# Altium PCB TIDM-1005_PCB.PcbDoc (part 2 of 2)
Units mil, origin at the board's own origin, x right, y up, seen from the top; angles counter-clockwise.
Board outline 3505 x 2975 mil, 2 copper layers (Top Layer, Bottom Layer), stack 62 mil thick; 159 components, 97 nets, 498 pads, 124 vias.
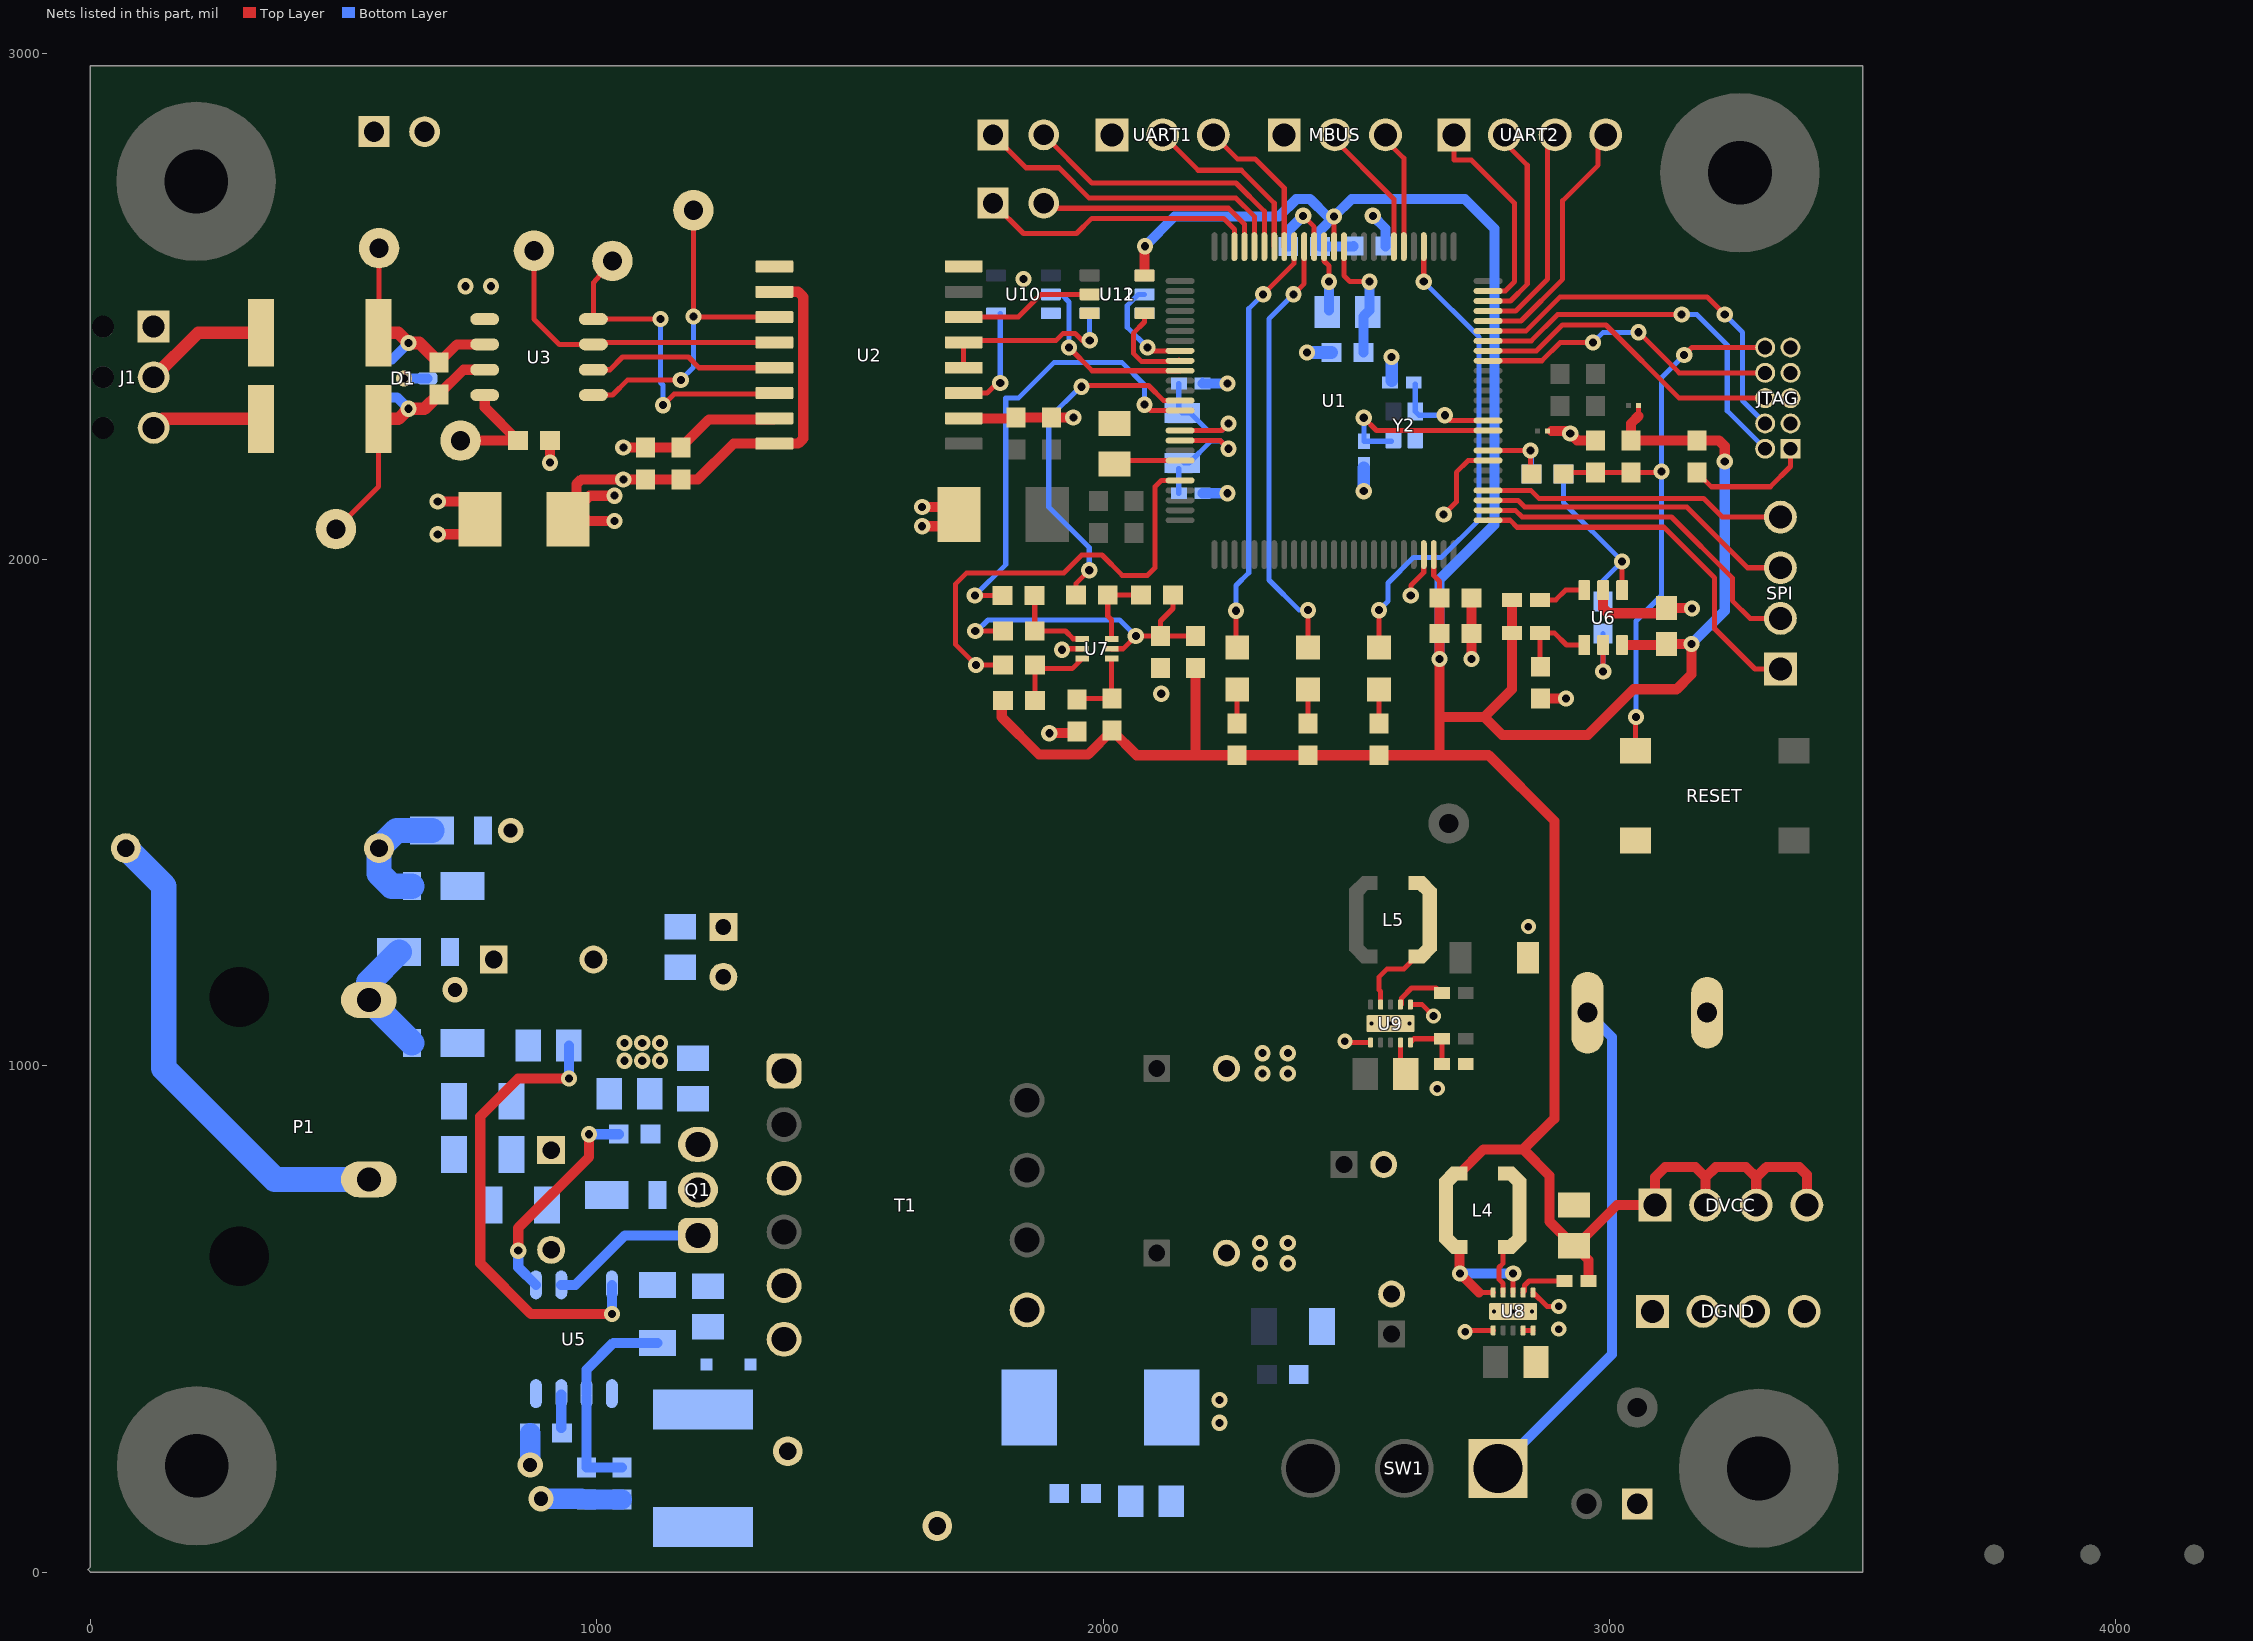
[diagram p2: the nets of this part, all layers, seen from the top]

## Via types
v1: diameter 32, hole 16, Top Layer to Bottom Layer, tented both sides, 88 vias
v2: diameter 32, hole 16, Top Layer to Bottom Layer, 19 vias
v3: diameter 30, hole 15, Top Layer to Bottom Layer, 7 vias
v4: diameter 19.68, hole 7.87, Top Layer to Bottom Layer, 6 vias
v5: diameter 50, hole 28, Top Layer to Bottom Layer, tented both sides, 3 vias
v6: diameter 50, hole 28, Top Layer to Bottom Layer, 1 vias

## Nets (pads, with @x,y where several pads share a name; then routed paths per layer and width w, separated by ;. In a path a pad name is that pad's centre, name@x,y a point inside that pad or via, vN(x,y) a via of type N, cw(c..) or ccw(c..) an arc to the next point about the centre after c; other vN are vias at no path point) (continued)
DGND: C1.1 C2.1 C3.2 C4.1 C5.1 C6.2 C7.1 C8.2 C9.1 C10.2 C15.2 C16.1 C26.2 C27.2 C28.2 C30.1 C31.1 C33.1 C34.2 C35.2 C36.2 C37.1 C38.1 C39.2 C40.2 D9.2 D10.2 DGND.1 DGND.2 DGND.3 DGND.4 J2.1 J3.2 JTAG.3 JTAG.5 JTAG.7 JTAG.9 MBUS.1 NT2.1 R2.2 R16.2 R17.2 R35.2 R93.2 RESET.3 U1.15 U1.72 U1.82 U2.2 U2.8 U6.2 U7.2 U8.1 U8.4 U8.5 U8.6 U8.11@2810,515 U9.1 U9.4 U9.6 U9.11@2567.72,1083.54 U10.3 U11.3 U12.3 UART1.1 Y2.2 | length 1959.5
  Top Layer w10: D10.2@1715.79,2088.81 D10.2@1715.79,2095.81 ; v1@1920.8,1823.81 U7.2@1958.66,1823.81 ; v1(2395.3,2678.81) 2416.93,2657.17 U1.15@2416.93,2617.94 ; v3@2480.12,1046.14 U9.1@2528.35,1046.14 ; C37.1@2587.4,993.86 U9.4@2587.4,1046.14 ; U9.6@2607.09,1120.94 2630.32,1120.94 v3(2652.72,1098.54) ; v1(2607.8,1928.81) 2607.8,1948.81 2633.47,1974.48 U1.72@2633.47,2009.67 ; v1(2672.8,2088.81) 2697.8,2113.81 2697.8,2172.27 2721.22,2195.7 U1.82@2760.43,2195.7 ; v3@2717.6,477.6 U8.1@2770.63,477.6 ; U8.4@2829.69,477.6 U8.5@2849.37,477.6 ; U8.6@2849.37,552.4 2876.77,525 v3(2900,525)
  Top Layer w20: v1(1642.8,2065.81) 1692.8,2065.81 D10.2@1715.79,2088.81 ; v1(1642.8,2103.81) 1707.8,2103.81 D10.2@1715.79,2095.81 ; U2.2@1724.8,2278.81 1826.3,2278.81 C15.2@1827.8,2280.3 C16.1@1897.8,2280.3 v1(1941.3,2280.3) ; v1@1900.39,1657.47 R93.2@1948.9,1657.47 ; v1(2727.8,1803.81) C8.2@2727.8,1853.81 C7.1@2727.8,1923.81 ; C34.2@2864.29,1725.3 v1(2914.29,1725.3) ; 2885.8,2253.81 2917.8,2253.81 v1(2922.8,2248.81) 2936.3,2235.3 C3.2@2972.8,2235.3 ; U6.2@2987.8,1939.44 2987.8,1903.81 2997.8,1893.81 3102.36,1893.81 C33.1@3112.8,1904.24 v1@3162.36,1904.24
  Bottom Layer w10: C1.1@2196.83,2347.47 C1.1@2196.83,2354.33
  Bottom Layer w20: C2.1@2196.83,2130.93 v1(2245.67,2130.93) ; C1.1@2196.83,2347.47 v1(2245.67,2347.47) ; C9.1@2365.75,2617.94 2365.75,2649.26 v1(2395.3,2678.81) ; v1(2532.8,2678.81) 2557.8,2653.81 C10.2@2557.8,2618.81
  Bottom Layer w25: v1(2402.8,2408.81) C6.2@2451.3,2408.81 ; v1(2515,2135) C4.1@2515,2181.38 ; C5.1@2570,2353.62 v1(2570,2400)
  other v1: 2310,610 2365,610 2310,650 2365,650 2315,985 2365,985 2315,1025 2365,1025 1893.9,1656.9 2115,1735 1918.9,1821.9 3163.27,1903.33
  other v2: 2230,295 2230,340 1842.8,2553.81
  other v3: 2715,475 2900,480 2660,955 2477.72,1048.54 2840,1275
  other v4: 2772.6,515 2810,515 2847.4,515 2530.32,1083.54 2567.72,1083.54 2605.12,1083.54
DVCC: C7.2 C8.1 C9.2 C10.1 C33.2 C35.1 DVCC.1 DVCC.2 DVCC.3 DVCC.4 L4.2 NT1.1 R1.2 R3.2 R5.2 R6.2 R25.2 R29.2 R30.2 R33.2 R90.2 R91.2 R98.2 U1.13 U1.73 U6.6 U8.8 U8.10 U12.5 | length 7621.8
  Top Layer w10: U1.13@2456.3,2617.94 v1(2456.3,2677.31) ; U1.73@2653.15,2009.67 2653.15,1968.45 2664.8,1956.8 C7.2@2664.8,1923.81 ; 2742.6,552.4 U8.10@2770.63,552.4 ; U8.8@2810,552.4 v2(2810,590) ; 3057.8,2283.81 NT1.1@3057.8,2303.81
  Top Layer w20: R91.2@1800,1722.15 1800,1688.65 1873.65,1615 1970.49,1615 R98.2@2017.8,1662.31 2066.6,1613.5 R25.2@2264.93,1613.5 R6.2@2405,1613.5 R5.2@2544.93,1613.5 2761.5,1613.5 2891.46,1483.54 2891.46,895 ; U12.5@2081.93,2561.21 v2@2081.93,2617.94 ; 2182.8,1616.3 R90.2@2182.8,1785.81 ; 2664.8,1613.7 2664.8,1688.81 ; C7.2@2664.8,1923.81 C8.1@2664.8,1853.81 v1(2664.8,1803.81) 2664.8,1688.81 ; v2@2704,591 L4.2@2704,642.5 ; L4.2@2704,787.5 2751.5,835 2830,835 ; v2(2705,590) 2742.6,552.4 ; R29.2@2807.68,1920.3 R30.2@2807.68,1855.3 2807.68,1743.69 2752.8,1688.81 ; 2890,895 2830,835 ; C35.1@2929.46,645 2881.5,692.96 2881.5,783.5 2830,835 ; R33.2@2958.62,575 2958.62,616.38 C35.1@2930,645 2935,645 3015,725 DVCC.1@3090,725 3090,780 3110,800 3170,800 3190,780 ; U6.6@3025.2,1831.17 3110.59,1831.17 C33.2@3112.8,1833.37 v1(3162.36,1833.37) 3162.36,1773.37 3132.8,1743.81 3047.8,1743.81 2957.8,1653.81 2787.8,1653.81 2752.8,1688.81 ; 3057.8,2283.81 3042.8,2268.81 R1.2@3042.8,2235.3 R3.2@3172.8,2235.3 3216.3,2235.3 3227.8,2223.81 v1(3227.8,2193.81) ; DVCC.2@3190,725 3190,780 ; DVCC.3@3290,725 3290,780 ; DVCC.4@3372.09,727.91 DVCC.4@3375,725 ; DVCC.4@3390,725 3390,785 3375,800 3310,800 3290,780 ; 2664.8,1688.81 2752.8,1688.81 ; 3190,780 3210,800 3270,800 3290,780
  Bottom Layer w20: v2(2082.8,2618.81) 2141.3,2677.31 2347.13,2677.31 2381.63,2711.81 2408.97,2711.81 2443.46,2677.31 v1(2456.3,2677.31) ; C10.1@2494.8,2618.81 2493.94,2617.94 C9.2@2428.74,2617.94 2428.74,2649.75 v1(2456.3,2677.31) ; v1(2664.8,1803.81) 2664.8,1960.81 2772.8,2068.81 2772.8,2653.81 2714.8,2711.81 2490.8,2711.81 v1(2456.3,2677.31) ; v2(2705,590) v2(2810,590) ; v1(3162.36,1833.37) 3227.8,1898.81 v1(3227.8,2193.81)
HFXIN: C5.2 U1.86 Y2.1 | length 205.7
  Top Layer w10: v1(2675,2285) 2685.56,2274.44 U1.86@2760.43,2274.44
  Bottom Layer w10: C5.2@2616.65,2346.97 Y2.1@2616.65,2292.56 2624.21,2285 v1(2675,2285)
HFXOUT: C4.2 U1.85 Y2.3 | length 356.8
  Top Layer w10: v1(2515,2280) 2540.25,2254.75 U1.85@2760.43,2254.75
  Bottom Layer w10: v1(2515,2280) C4.2@2515,2233.62 Y2.3@2569.53,2233.62
I2C_SCL: R96.2 U1.39 | length 905.2
  Top Layer w10: v1(1746.8,1928.81) R96.2@1801.3,1928.81 ; v1(2081.8,2305.81) 2093.48,2294.12 U1.39@2152.17,2294.12
  Bottom Layer w10: v1(1746.8,1928.81) 1807.8,1989.81 1807.8,2318.81 1832.8,2318.81 1902.8,2388.81 2037.8,2388.81 2081.8,2344.81 v1(2081.8,2305.81)
I2C_SDA: R97.2 U1.38 | length 691.8
  Top Layer w10: R97.2@1946.3,1929.81 1946.3,1952.31 v1(1972.8,1978.81) ; v1(1957.3,2341.31) 1959.8,2343.81 2089.8,2343.81 2119.8,2313.81 U1.38@2152.17,2313.81
  Bottom Layer w10: v1(1957.3,2341.31) 1955.3,2341.31 1892.8,2278.81 1892.8,2103.81 1972.8,2023.81 v1(1972.8,1978.81)
INTERRUPT: R92.2 U1.46 | length 883.7
  Top Layer w10: v1@1743.9,1796.9 1708.9,1831.9 1708.9,1951.9 1730.8,1973.81 1922.8,1973.81 1957.8,2008.81 1997.8,2008.81 2037.8,1968.81 2087.8,1968.81 2102.8,1983.81 2102.8,2143.81 2115.32,2156.33 U1.46@2152.17,2156.33 ; v1(1748.9,1791.9) R92.2@1808.27,1791.9
LED1: LED1.2 U1.4 | length 951
  Top Layer w10: LED1.2@2545,1826.34 v1(2545,1900) ; v1(2633.47,2548.81) U1.4@2633.47,2617.94
  Bottom Layer w10: v1(2545,1900) 2562.8,1917.8 2562.8,1953.81 2612.8,2003.81 2667.8,2003.81 2742.8,2078.81 2742.8,2439.48 v1(2633.47,2548.81)
LED2: LED2.2 U1.16 | length 862.7
  Top Layer w10: v1(2376.3,2523.81) 2397.25,2544.75 U1.16@2397.25,2617.94 ; LED2.2@2405,1826.34 v1(2405,1900)
  Bottom Layer w10: v1(2376.3,2523.81) 2327.8,2475.3 2327.8,1959.51 2387.3,1900 v1(2405,1900)
LED3: LED3.2 U1.17 | length 838.9
  Top Layer w10: LED3.2@2262.8,1828.54 v1(2262.8,1898.81) ; v1(2316.3,2523.81) 2377.56,2585.07 U1.17@2377.56,2617.94
  Bottom Layer w10: v1(2262.8,1898.81) 2262.8,1948.81 2287.8,1973.81 2287.8,2495.3 v1(2316.3,2523.81) v1@2317.67,2522.44
MBUS_RXD: MBUS.3 U1.6 | length 240
  Top Layer w10: MBUS.3@2547.8,2838.81 2594.1,2792.51 U1.6@2594.1,2617.94
MBUS_TXD: MBUS.2 U1.7 | length 273.3
  Top Layer w10: MBUS.2@2447.8,2838.81 2574.41,2712.19 U1.7@2574.41,2617.94
NetC17_1: C17.1 C18.2 C32.1 D11.1 TP3.1 U2.10 U2.16 U3.8 | length 1258.8
  Top Layer w20: TP3.1@746.09,2234.83 C32.1@844.6,2234.83 778.81,2300.62 U3.8@778.81,2324.83 ; v1(1034.83,2076.09) 983.57,2076.09 D11.1@959.83,2099.83 ; v1(1034.83,2126.09) 986.09,2126.09 D11.1@959.83,2099.83 ; 1267.99,2226.73 1199.6,2158.33 C18.2@1166.09,2158.33 C17.1@1096.09,2158.33 v1(1052.59,2158.33) 969.6,2158.33 959.83,2148.57 D11.1@959.83,2099.83 ; 1270.07,2228.81 U2.16@1350.79,2228.81 1397.8,2228.81 1407.8,2238.81 1407.8,2518.81 1397.8,2528.81 U2.10@1350.79,2528.81
NetC22_1: C22.1 R13.2 R15.1
NetC22_2: C22.2 C24.1 L3.2 R12.2 R13.1 R14.1 T1.1
NetC23_1: C23.1 D3.1 D4.1 L3.1 R12.1
NetC25_1: C25.1 R16.1
NetC25_2: C25.2 D9.1 T1.7
NetC29_2: C29.2 D8.1 U5.1
NetC31_2: C31.2 R90.1 R94.2 R95.2 U7.5 | length 661.3
  Top Layer w10: v1(1747.66,1858.81) R95.2@1802.17,1858.81 ; U7.5@2016.93,1823.81 2039.8,1823.81 v1(2064.8,1848.81) C31.2@2113.66,1848.81 ; R94.2@2138.29,1929.81 2138.29,1903.3 2113.66,1878.67 C31.2@2113.66,1848.81 ; R90.1@2182.8,1848.81 C31.2@2113.66,1848.81
  Bottom Layer w10: v1(1747.66,1858.81) 1750.8,1858.81 1772.66,1880.67 2032.93,1880.67 v1(2064.8,1848.81)
NetC34_1: C34.1 R30.1 U6.4 | length 168.2
  Top Layer w10: C34.1@2864.29,1788.29 2862.8,1786.8 R30.1@2862.8,1855.3 2891.3,1855.3 2915.43,1831.17 U6.4@2950.4,1831.17
NetD1_1: D1.1 R7.1 R8.1 TP8.1 U3.7 | length 569
  Top Layer w10: TP8.1@485,2060 569.3,2144.3 R8.1@569.3,2277.72
  Top Layer w20: R7.1@688.16,2326.22 736.77,2374.83 U3.7@778.81,2374.83
  Top Layer w25: R8.1@569.3,2277.72 608.16,2277.72 v1(628.16,2297.72) 659.66,2297.72 R7.1@688.16,2326.22
  Bottom Layer w20: D1.1@570.92,2320.32 605.56,2320.32 v1(628.16,2297.72)
NetD1_2: D1.2 R7.2 R9.1 TP9.1 U3.6 | length 486.8
  Top Layer w10: R9.1@569.3,2447.72 570,2448.42 TP9.1@570,2615
  Top Layer w20: R7.2@688.16,2389.22 723.78,2424.83 U3.6@778.81,2424.83
  Top Layer w25: R9.1@569.3,2447.72 608.16,2447.72 v1(628.16,2427.72) 649.66,2427.72 R7.2@688.16,2389.22
  Bottom Layer w20: D1.2@570.92,2395.12 595.56,2395.12 v1(628.16,2427.72)
NetD3_2: D3.2 D5.1 F1.1 | length 244.5
  Bottom Layer w50: D3.2@634.8,1355 595,1355 570,1380 F1.1@570,1430 605,1465 D5.1@674.8,1465
NetD4_2: D4.2 D6.1 P1.1 | length 239.8
  Bottom Layer w50: P1.1@549.92,1129.88 D4.2@634.8,1045 ; P1.1@549.92,1130 549.92,1165.12 D6.1@609.8,1225
NetD7_1: D7.1 R15.2
NetD7_2: D7.2 Q1.2 T1.3
NetD8_2: D8.2 R18.1
NetF1_2: F1.2 P1.2 | length 961.8
  Bottom Layer w50: F1.2@70,1430 145,1355 145,995 364.33,775.67 P1.2@549.92,775.67
NetJ1_2: J1.2 R9.2 | length 248.4
  Top Layer w25: J1.2@125,2360 212.72,2447.72 R9.2@337.02,2447.72
NetJ1_3: J1.3 R8.2 | length 219.4
  Top Layer w25: J1.3@125,2260 142.72,2277.72 R8.2@337.02,2277.72
NetJ3_1: J3.1 SW1.1 | length 1027.3
  Bottom Layer w10: J3.1@2946.89,1145 J3.1@2956.89,1155
  Bottom Layer w20: SW1.1@2780.04,205 2946.89,371.85 3005,429.96 3005,1056.89 J3.1@2956.89,1105
NetJTAG_1: JTAG.1 R3.1 | length 248.4
  Top Layer w10: R3.1@3172.8,2172.31 3201.3,2143.81 3317.8,2143.81 3357.8,2183.81 JTAG.1@3357.8,2218.81
NetL1_1: L1.1 U1.14 | length 134.6
  Top Layer w10: U1.14@2436.62,2617.94 2436.62,2589.67 2446.3,2579.98 v1(2446.3,2548.81)
  Bottom Layer w10: L1.1@2442.8,2488.81 L1.1@2446.3,2492.31
  Bottom Layer w20: L1.1@2446.3,2492.31 v1(2446.3,2548.81)
NetL4_1: L4.1 U8.9 | length 99.3
  Top Layer w10: U8.9@2790.32,552.4 2790.32,570.09 2782,578.4 2782,601.6 2790.32,609.91 2790.32,636.82 L4.1@2796,642.5
NetL5_1: L5.1 U9.9 | length 146.5
  Top Layer w10: U9.9@2548.03,1120.94 2548.03,1146.99 2544.72,1150.31 2544.72,1175.14 2561.12,1191.54 2594.22,1191.54 L5.1@2618.72,1216.04
NetLED1_1: LED1.1 R5.1 | length 67.1
  Top Layer w10: R5.1@2545,1676.56 LED1.1@2545,1743.66
NetLED2_1: LED2.1 R6.1 | length 67.2
  Top Layer w10: R6.1@2405,1676.5 LED2.1@2405,1743.66
NetLED3_1: LED3.1 R25.1 | length 67.1
  Top Layer w10: R25.1@2265,1676.56 LED3.1@2265,1743.66
NetQ1_1: Q1.1 U5.6 | length 310.6
  Bottom Layer w20: U5.6@930,567.28 957.72,567.28 1055.67,665.24 Q1.1@1200,665.24
NetQ1_3: Q1.3 R20.2 R23.1 R24.1
NetR2_1: R2.1 U1.44 | length 132.2
  Top Layer w10: R2.1@2022.8,2188.81 2029.69,2195.7 U1.44@2152.17,2195.7
NetR4_2: R4.2 R31.2 U1.83 | length 183.5
  Top Layer w10: U1.83@2760.43,2215.38 v1(2844.37,2215.38) 2844.37,2170.74 R4.2@2846.3,2168.81
  Bottom Layer w10: R31.2@2846.3,2168.81 2846.3,2213.45 v1(2844.37,2215.38) v1@2847.8,2218.81
NetR14_2: R14.2 U5.8 | length 919.8
  Top Layer w20: v2(945,975) 845,975 770,900 770,610 870,510 v2(1030,510)
  Bottom Layer w20: v2(945,975) R14.2@945,1040 ; v2(1030,510) U5.8@1030,567.28
NetR18_2: R18.2 R19.1 T1.5
NetR19_2: R19.2 R21.1 R22.1 U5.2 | length 418.2
  Bottom Layer w20: U5.2@980,345.52 R21.1@980,206.5 R22.1@1050,206.5 ; U5.2@980,352.72 980,400 1032.91,452.91 R19.2@1120,452.91
NetR20_1: R20.1 U5.5 | length 428.7
  Top Layer w20: v2(845,635) 845,680 985,820 v2(985,865)
  Bottom Layer w20: v2(845,635) 845,602.28 U5.5@880,567.28 ; v2(985,865) R20.1@1043.5,865
NetR29_1: R29.1 U6.3 | length 95.5
  Top Layer w10: R29.1@2862.8,1920.3 2894.29,1920.3 2913.43,1939.44 U6.3@2950.4,1939.44
NetR32_2: R32.2 U6.5 | length 127.4
  Top Layer w10: v1(2987.8,1778.81) U6.5@2987.8,1831.17
  Bottom Layer w10: v1(2987.8,1778.81) R32.2@2987.8,1853.81
NetR33_1: R33.1 U8.7 | length 97.4
  Top Layer w10: U8.7@2829.69,552.4 2832.45,555.17 2832.45,566.06 2841.39,575 R33.1@2911.38,575
NetR34_2: R34.2 R35.1 U9.5 | length 115.1
  Top Layer w10: U9.5@2607.09,1046.14 2614.49,1053.54 R34.2@2669.09,1053.54 R35.1@2669.09,1003.54
NetR36_1: R36.1 U9.7 | length 105.3
  Top Layer w10: U9.7@2589.72,1120.94 2589.72,1134.16 2609.1,1153.54 2657.72,1153.54 R36.1@2669.09,1142.17
NetR91_1: R91.1 R92.1 U7.3 | length 159.6
  Top Layer w10: R91.1@1865.39,1721.9 1865.39,1776.97 1872.86,1784.44 1938.98,1784.44 U7.3@1958.66,1804.12
NetR93_1: R93.1 R98.1 U7.4 | length 154.2
  Top Layer w10: R93.1@1942.8,1725.3 R98.1@2017.8,1725.3 2016.93,1726.17 U7.4@2016.93,1804.12
NetR94_1: R94.1 R97.1 U7.6 | length 155.5
  Top Layer w10: U7.6@2016.93,1843.49 2016.93,1880.67 2009.29,1888.31 R97.1@2009.29,1929.81 R94.1@2075.3,1929.81
NetR95_1: R95.1 R96.1 U7.1 | length 169
  Top Layer w10: R96.1@1865.16,1927.94 R95.1@1865.16,1858.81 1925.8,1858.81 1941.11,1843.49 U7.1@1958.66,1843.49
NetRT1_1: RT1.1 U5.3 | length 66.2
  Bottom Layer w20: RT1.1@930,285 U5.3@930,351.22
NetTP4_1: TP4.1 U2.14 U3.4 | length 664.8
  Top Layer w10: TP4.1@1031.09,2589.83 993.37,2547.11 U3.4@993.37,2474.83 v1(1126.09,2474.83) ; v1(1131.09,2304.83) 1153.09,2326.83 1350.79,2326.83 U2.14@1350.79,2328.81
  Bottom Layer w10: v1(1126.09,2474.83) 1126.09,2349.83 1131.09,2344.83 v1(1131.09,2304.83)
NetTP5_1: TP5.1 U2.11 U3.1 | length 690.6
  Top Layer w10: U3.1@993.37,2324.83 1031.09,2324.83 1061.09,2354.83 v1(1166.09,2354.83) ; TP5.1@1191.09,2689.83 v1(1191.09,2479.83) 1192.12,2478.81 U2.11@1350.79,2478.81
  Bottom Layer w10: v1(1166.09,2354.83) 1191.09,2379.83 v1(1191.09,2479.83)
NetTP6_1: TP6.1 U2.12 U3.3 | length 632.1
  Top Layer w10: TP6.1@876.09,2609.83 876.09,2474.83 926.09,2424.83 U3.3@993.37,2424.83 997.35,2428.81 U2.12@1350.79,2428.81
NetU2_3: U2.3 U10.4 | length 223
  Top Layer w10: U2.3@1724.8,2328.81 1771.06,2328.81 1791.06,2348.81 v2@1802.8,2348.81
  Bottom Layer w10: v2(1796.93,2348.81) U10.4@1796.93,2485.54
NetU2_4: U2.4 U2.5 U11.4 | length 359.7
  Top Layer w10: U2.4@1724.8,2378.81 U2.5@1724.8,2428.81 ; U2.5@1728.94,2432.94 1907.33,2432.94 1921.2,2446.81 1944.39,2446.81 1958.26,2432.94 v2(1973.66,2432.94)
  Bottom Layer w10: v2(1973.66,2432.94) U11.4@1973.66,2486.41
NetU2_6: U2.6 U12.2 | length 267.5
  Top Layer w10: U2.6@1724.8,2478.81 1832.48,2478.81 1877.48,2523.81 U12.2@1973.66,2523.81
NetU2_13: U2.13 U3.2 | length 376.5
  Top Layer w10: U3.2@993.37,2374.83 1026.09,2374.83 1051.09,2399.83 1181.09,2399.83 1202.12,2378.81 U2.13@1350.79,2378.81
P1.4: SPI.1 U1.76 | length 757.6
  Top Layer w10: U1.76@2760.43,2077.59 2804.02,2077.59 2817.8,2063.81 3107.8,2063.81 3207.8,1963.81 3207.8,1863.81 3287.8,1783.81 SPI.1@3337.8,1783.81
P1.5: SPI.2 U1.77 | length 692.1
  Top Layer w10: U1.77@2760.43,2097.27 2814.33,2097.27 2827.8,2083.81 3122.8,2083.81 3242.8,1963.81 3242.8,1918.81 3277.8,1883.81 SPI.2@3337.8,1883.81
P1.6: SPI.3 U1.78 | length 632.5
  Top Layer w10: U1.78@2760.43,2116.96 2819.65,2116.96 2832.8,2103.81 3152.8,2103.81 3272.8,1983.81 SPI.3@3337.8,1983.81
P1.7: SPI.4 U1.79 | length 599.2
  Top Layer w10: U1.79@2760.43,2136.64 2844.96,2136.64 2860.8,2120.81 3185.8,2120.81 3222.8,2083.81 SPI.4@3337.8,2083.81
P2.4: GPIO1.2 U1.20 | length 568.3
  Top Layer w10: GPIO1.2@1882.8,2838.81 1977.8,2743.81 2262.8,2743.81 2318.51,2688.1 U1.20@2318.51,2617.94
P2.5: GPIO1.1 U1.21 | length 642.6
  Top Layer w10: GPIO1.1@1782.8,2838.81 1847.8,2773.81 1912.8,2773.81 1972.8,2713.81 2262.8,2713.81 2298.82,2677.78 U1.21@2298.82,2617.94
P2.6: GPIO2.2 U1.22 | length 458
  Top Layer w10: GPIO2.2@1882.8,2703.81 1892.8,2693.81 2247.8,2693.81 2279.14,2662.47 U1.22@2279.14,2617.94
P2.7: GPIO2.1 U1.23 | length 557.1
  Top Layer w10: GPIO2.1@1782.8,2703.81 1842.8,2643.81 1947.8,2643.81 1977.8,2673.81 2237.8,2673.81 2259.45,2652.15 U1.23@2259.45,2617.94
PGND: C23.2 C24.2 C29.1 C30.2 D5.2 D6.2 R21.2 R22.2 R23.2 R24.2 RT1.2 T1.6 U5.4 | length 213.5
  Bottom Layer w40: v5(868.5,211.5) RT1.2@868.5,275 ; v5(890,145) R21.2@970,145 ; R21.2@980,143.5 R22.2@1050,143.5
  other v1: 1055,1010 1090,1010 1055,1045 1090,1045 1125,1045
  other v2: 1125,1010
  other v5: 830,1465
  other v6: 720,1150
RS485_EN: U1.33 U11.2 | length 209.7
  Top Layer w10: v1(2087.8,2418.81) 2094.37,2412.23 U1.33@2152.17,2412.23
  Bottom Layer w10: U11.2@2081.93,2523.81 2070.08,2523.81 2047.84,2501.57 2047.84,2458.76 v1(2087.8,2418.81)
RS485_GND: C17.2 C18.1 C32.2 D1.3 D11.2 J1.1 RS485_GND.1 RS485_GND.2 U2.9 U2.15 U3.5 | length 605.8
  Top Layer w20: v1(686.09,2049.83) 736.09,2049.83 771.09,2084.83 741.09,2114.83 v1(686.09,2114.83) ; v1(907.59,2191.33) C32.2@907.59,2234.83 ; v1(1052.59,2221.33) C17.2@1096.09,2221.33 C18.1@1166.09,2221.33 1221.5,2276.73 U2.15@1348.72,2276.73
  Bottom Layer w20: v1(619.15,2357.72) D1.3@665.4,2357.72
  other v1: 741.09,2539.83 791.09,2539.83
RS485_RXD: U1.34 U12.4 | length 191.8
  Top Layer w10: U12.4@2081.93,2486.41 2081.93,2468.94 2059.8,2446.81 2059.8,2407.21 2076.2,2390.81 2150.39,2390.81 2150.39,2394.33 U1.34@2152.17,2392.55
RS485_TXD: U1.35 U10.2 | length 370.5
  Top Layer w10: v2(1932.8,2418.81) 1978.74,2372.86 U1.35@2152.17,2372.86
  Bottom Layer w10: U10.2@1896.93,2523.81 1917.8,2523.81 1932.8,2508.81 v2(1932.8,2418.81)
RST: C3.1 JTAG.10 R1.1 R4.1 RESET.4 | length 1183.2
  Top Layer w10: R4.1@2909.29,2168.81 2912.8,2172.31 C3.1@2972.8,2172.31 R1.1@3042.8,2172.31 3101.3,2172.31 v1(3102.8,2173.81) ; RESET.4@3051.3,1622.39 3051.3,1687.31 v1(3052.8,1688.81) ; v1(3147.8,2403.81) 3162.8,2418.81 JTAG.10@3307.8,2418.81
  Bottom Layer w10: v1(3052.8,1688.81) 3052.8,1878.81 3102.8,1928.81 v1(3102.8,2173.81) 3102.8,2358.81 v1(3147.8,2403.81)
RST_POR: R31.1 R32.1 U6.1 | length 376.6
  Top Layer w10: U6.1@3024.29,1940.34 U6.1@3025.2,1939.44 v1(3025.2,1996.41)
  Bottom Layer w10: R31.1@2909.29,2168.81 2909.29,2112.31 v1(3025.2,1996.41) 2987.8,1959 R32.1@2987.8,1916.8 R32.1@2989.8,1918.81
TCK: JTAG.4 U1.95 | length 757.8
  Top Layer w10: U1.95@2760.43,2451.6 2835.59,2451.6 2902.8,2518.81 3192.8,2518.81 v1(3227.8,2483.81)
  Bottom Layer w10: v1(3227.8,2483.81) 3262.8,2448.81 3262.8,2313.81 JTAG.4@3307.8,2268.81
TDI: JTAG.8 U1.92 | length 603.8
  Top Layer w10: U1.92@2760.43,2392.55 2866.54,2392.55 2902.8,2428.81 v1(2967.8,2428.81) ; v1(3057.8,2448.81) 3137.8,2368.81 JTAG.8@3307.8,2368.81
  Bottom Layer w10: v1(2967.8,2428.81) 2987.8,2448.81 v1(3057.8,2448.81)
TDO: JTAG.6 U1.93 | length 628.3
  Top Layer w10: U1.93@2760.43,2412.23 2856.22,2412.23 2907.22,2463.23 2993.38,2463.23 3137.8,2318.81 JTAG.6@3307.8,2318.81
TMS: JTAG.2 U1.94 | length 754.8
  Top Layer w10: U1.94@2760.43,2431.92 2845.91,2431.92 2897.8,2483.81 v1(3142.8,2483.81)
  Bottom Layer w10: v1(3142.8,2483.81) 3172.8,2483.81 3232.8,2423.81 3232.8,2293.81 JTAG.2@3307.8,2218.81
UART_CTRL1: U1.97 UART2.3 | length 428.4
  Top Layer w10: U1.97@2760.43,2490.97 2814.96,2490.97 2877.8,2553.81 UART2.3@2877.8,2838.81
UART_CTRL2: U1.96 UART2.4 | length 495.5
  Top Layer w10: U1.96@2760.43,2471.29 2825.28,2471.29 2907.8,2553.81 2907.8,2708.81 2977.8,2778.81 UART2.4@2977.8,2838.81
UART_RXD1: U1.18 UART1.3 | length 299.4
  Top Layer w10: UART1.3@2217.8,2838.81 2265.26,2791.35 2300.34,2791.35 2357.88,2733.81 U1.18@2357.88,2617.94
UART_RXD2: U1.98 UART2.2 | length 410.9
  Top Layer w10: U1.98@2760.43,2510.66 2804.65,2510.66 2837.8,2543.81 2837.8,2778.81 UART2.2@2777.8,2838.81
UART_TXD1: U1.19 UART1.2 | length 362.2
  Top Layer w10: UART1.2@2117.8,2838.81 2187.8,2768.81 2273.19,2768.81 2338.19,2703.81 U1.19@2338.19,2617.94
UART_TXD2: U1.99 UART2.1 | length 420.2
  Top Layer w10: UART2.1@2692.8,2838.81 2692.8,2788.81 2727.8,2788.81 2812.8,2703.81 2812.8,2548.81 2794.33,2530.34 U1.99@2760.43,2530.34
VCORE: C6.1 L1.2 U1.12 | length 257.5
  Top Layer w10: U1.12@2475.99,2617.94 2475.99,2560.62 2487.8,2548.81 v1(2526.3,2548.81)
  Bottom Layer w10: L1.2@2522.8,2488.81 L1.2@2526.3,2492.31
  Bottom Layer w20: C6.1@2514.29,2408.81 2514.29,2480.3 L1.2@2522.8,2488.81 ; L1.2@2526.3,2492.31 v1(2526.3,2548.81)
XIN: C1.2 U1.41 Y1.1 | length 260.4
  Top Layer w10: U1.41@2152.17,2254.75 2233.74,2254.75 v1(2247.8,2268.81)
  Bottom Layer w10: Y1.1@2149.58,2299.97 C1.2@2149.58,2347.47 ; Y1.1@2156.43,2289.2 2172.4,2289.2 2206.85,2254.75 2233.74,2254.75 v1(2247.8,2268.81)
XOUT: C2.2 U1.42 Y1.2 | length 262.9
  Top Layer w10: U1.42@2152.17,2235.07 2231.54,2235.07 v1(2247.8,2218.81)
  Bottom Layer w10: C2.2@2149.58,2130.93 Y1.2@2149.58,2180.01 ; Y1.2@2160.35,2190.78 2169.77,2190.78 2212.8,2233.81 2232.8,2233.81 v1(2247.8,2218.81)
pads on no net: FID1.1 FID2.1 FID3.1 FID4.1 FID5.1 FID6.1 H1.1 H2.1 H3.1 H4.1 H5.0 H6.0 H7.0 H8.0 J1.4 J1.5 J1.6 LBL1.0 P1.MH1 P1.MH2 RESET.1 RESET.2 T1.2 T1.4 T1.8 T1.9 U1.1 U1.2 U1.3 U1.5 U1.8 U1.9 U1.10 U1.11 U1.24 U1.25 U1.26 U1.27 U1.28 U1.29 U1.30 U1.31 U1.32 U1.36 U1.37 U1.47 U1.48 U1.49 U1.50 U1.51 U1.52 U1.53 U1.54 U1.55 U1.56 U1.57 U1.58 U1.59 U1.60 U1.61 U1.62 U1.63 U1.64 U1.65 U1.66 U1.67 U1.68 U1.69 U1.70 U1.71 U1.74 U1.75 U1.80 U1.81 U1.88 U1.89 U1.90 U1.91 U1.100 U2.7 U8.11@2784.8,515 U8.11@2835.2,515 U9.11@2542.52,1083.54 U9.11@2592.91,1083.54 U10.1 U11.1 U12.1 Y2.4

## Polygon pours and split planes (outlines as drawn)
DGND on Bottom Layer "BOTTOM_LAYER_DGND_P105" (solid, remove dead copper, pour order 105): 1680,2975 1680,2200 1680,2180 1620,2120 1620,1790 1625,1785 1870,1540 1875,1540 2355,1540 2445,1460 2445,1285 2335,1175 1910,1175 1902.5,1175 1787.5,1060 1785,1057.5 1785,380 1625,253.43 1625,220 1625,0 3500,0 3500,2970 3495,2975
NetC25_1 on Bottom Layer "BOTTOM_LAYER_NETC25_1_P100" (solid, remove dead copper, pour order 100): 2090,200 2090,60 1955,60 1955,200 2090,200
24VDC on Bottom Layer "BOTTOM_LAYER_24VDC_P098" (solid, remove dead copper, pour order 98): 2355,520.43 2355,475 2355,435 2355,361.46 2475,280 2475,85 2425,35 2260,35 2260,323.03 2170,467.5 2130,467.5 2062.5,467.5 1970,530 1970,560 1970,607.6 1972.72,610.32 1888.03,695 1787.5,695 1787.5,872.5 1787.5,1060 1860,1140 2125,1140 2180,1055 2180,600 2255,540 2335.43,540
NetC25_2 on Bottom Layer "BOTTOM_LAYER_NETC25_2_P096" (solid, remove dead copper, pour order 96): 1835,565 1887.5,600 1950,600 1950,265 1950,40 1940,40 1790,40 1790,535
PGND on Bottom Layer "BOTTOM_LAYER_PGND_P093" (solid, remove dead copper, pour order 93): 750,1510 750,1425 750,1315 690,1270 690,1182.44 690,1140 690,1111.03 820,990 820,525.63 820,440 820,320 820,0 1420,0 1425,5 1425,1270 1185,1510
NetD8_2 on Bottom Layer "BOTTOM_LAYER_NETD8_2_P091" (solid, remove dead copper, pour order 91): 1175,515 1175,445 1189,431 1245,431 1260,410 1275,390 1281.43,380 1350,380 1350,420 1340,420 1290,470 1290,515
NetC29_2 on Bottom Layer "BOTTOM_LAYER_NETC29_2_P085" (solid, remove dead copper, pour order 85): 1005,400 1005,300 1020,275 1032,255 1310,255 1340,285 1340,345 1311.58,373.42 1276.58,373.42 1275,375 1260,375 1245,390 1245,415 1245,420.5 1235,430.5 1189,430.5 1160,401.5 1160,400
NetC22_2 on Bottom Layer "BOTTOM_LAYER_NETC22_2_P081" (solid, remove dead copper, pour order 81): 1420,885 1420,1105 1420,1115 1305,1230 1100,1230 1000,1157.5 892.5,1157.5 860,1125 815,1080 815,1005.41 781.26,961.67 780,960.41 780,778.74 781.26,780 925,780 935,780 960,805 960,950 960,956.46 900,1010 900,1045 900,1080 918.18,1098.18 952.5,1097.5 1107.5,1097.5 1212.5,1097.5 1240,1070 1305,1005 1305,1000 1305,885
NetR18_2 on Bottom Layer "BOTTOM_LAYER_NETR18_2_P079" (solid, remove dead copper, pour order 79): 1420,605 1420,525 1063.27,525 1063.27,605.67 1419.33,605.67
NetD7_1 on Bottom Layer "BOTTOM_LAYER_NETD7_1_P077" (solid, remove dead copper, pour order 77): 1070,784.5 1070,675 835,675 835,771.26 836.38,772.64 939.49,772.64 942.14,772.64 954,784.5 1070,784.5
NetD7_2 on Bottom Layer "BOTTOM_LAYER_NETD7_2_P075" (solid, remove dead copper, pour order 75): 1420,875 1420,760 1395,715 1100,705 1075,705 1075,730 1075,745 1075,780 1090,800 1260,800 1258.57,801.43 1280,830 1298.43,854.57 1313.75,875 1375,875 1415,875
NetQ1_3 on Bottom Layer "BOTTOM_LAYER_NETQ1_3_P073" (solid, remove dead copper, pour order 73): 1070,990 1070,800 1255,800 1290,846 1290,990
NetC22_1 on Bottom Layer "BOTTOM_LAYER_NETC22_1_P071" (solid, remove dead copper, pour order 71): 675,985 675,715 698.74,686.26 715,665 835,665 825,675 825,771.26 783.74,771.26 750,805 750,985
NetC23_1 on Bottom Layer "BOTTOM_LAYER_NETC23_1_P063" (solid, remove dead copper, pour order 63): 690,1410 690,995 805,995 820,995 820,1070 875,1130 992.5,1242.5 967.5,1242.5 905.58,1180.58 967.5,1242.5 945,1242.5 1315,1242.5 1315,1275 1315,1300 1290,1315 1260,1335 885,1335 815,1410 760,1410
RS485_GND on Bottom Layer "BOTTOM_LAYER_RS485_GND_P061" (solid, remove dead copper, pour order 61): -5,2975 -5,1980 630,1980 1253.9,1980 1415,2175 1415,2370 1415,2975 1253.9,2975 640,2975
DGND on Top Layer "TOP_LAYER_DGND_P113" (solid, remove dead copper, pour order 113): 1680,2975 1680,2200 1680,2180 1620,2120 1620,1790 1625,1785 1870,1540 1875,1540 2355,1540 2445,1460 2445,1375 2445,1285 2335,1175 1910,1175 1902.5,1175 1787.5,1060 1785,1057.5 1785,380 1625,253.43 1625,220 1625,0 3500,0 3500,2970 3495,2975
RS485_GND on Top Layer "TOP_LAYER_RS485_GND_P103" (solid, remove dead copper, pour order 103): 0,1980 1253.9,1980 1415,2175 1415,2975 -5,2975 -5,1980
PGND on Top Layer "TOP_LAYER_PGND_P095" (solid, remove dead copper, pour order 95): 752.75,1502.25 752.75,1427.75 752.75,1350 690,1270 690,1182.44 690,1145 690,1110 820,995 820,530 820,440 820,320 820,0 1420,0 1425,5 1425,1270 1185,1510 752.75,1510
NetC17_1 on Top Layer "TOP_LAYER_NETC17_1_P053" (solid, remove dead copper, pour order 53): 751.09,2309.83 751.09,2339.83 976.09,2339.83 976.09,2174.83 1186.09,2174.83 1186.09,2054.83 941.09,2054.83 846.09,2149.83 751.09,2244.83

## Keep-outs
Keep-Out Layer:
  lines w5: 25,25 25,2950 3470,2950 3470,25 25,25
  text ".Layer_Name" at 577,-858.49 h60

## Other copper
Top Layer:
  text ".Layer_Name" at 577,-858.49 h60
Bottom Layer:
  text ".Layer_Name" at 577,-858.49 h60

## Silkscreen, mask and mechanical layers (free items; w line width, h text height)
Top Overlay:
  lines w6: 1917.8,2008.81 1949.08,2008.81 1964.1,2023.82
  text "P2.5" at 1735,2900 h50.84
  text "P2.4" at 1852.8,2898.81 h50.84
  text "CAUTION JTAG/IO Port Not Isolated" at 865,2850 h50
  text "CTRL1" at 2885,2775 h50.84 r270
  text "CTRL2" at 2973.99,2775 h50.84 r270
  text "DGND" at 2295,2747 h50.84
  text "DGND" at 1955,2745 h50.84
  text "TX" at 2435,2745 h50.84
  text "RX" at 2530,2745 h50.84
  text "TX" at 2670,2745 h50.84
  text "RX" at 2765,2745 h50.84
  text "TX" at 2095,2743.81 h50.84
  text "RX" at 2190,2743.81 h50.84
  text "P2.7" at 1735,2610 h50.84
  text "P2.6" at 1845,2610 h50.84
  text "GND" at 290,2420 h50.84 r90
  text "RST" at 3172.8,2403.81 h30
  text "GND" at 3442.8,2358.81 h30 r90
  text "TDI" at 3172.8,2353.81 h30
  text "A" at 290,2345 h50.84 r90
  text "TDO" at 3167.8,2298.81 h30
  text "GND" at 3442.8,2258.81 h30 r90
  text "B" at 290,2250 h50.84 r90
  text "TCK" at 3252.8,2203.81 h30 r90
  text "PU" at 3442.8,2188.81 h30 r90
  text "RS-485" at 55,2155 h50.84
  text "TMS" at 3217.8,2143.81 h30
  text "P1.7" at 3435,2060 h50.84 r90
  text "P1.6" at 3435,1950 h50.84 r90
  text "P1.5" at 3435,1840 h50.84 r90
  text "P1.4" at 3435,1735 h50.84 r90
  text "24V@0.5A" at 3105,880 h50.84
  text "3.3V" at 3345,795 h50.84
  text "85VAC-264VAC 50/60Hz" at 30,390 h50.84
  text "85VAC-264VAC 50/60Hz" at -1890,220 h50.84 r270
  text "24VDC" at 2865,35 h50.84
  text "DGND" at 3025,35 h50.84
  text "24VDC (J3)" at 2240,25 h50.84
  text "AC/DC (P1)" at 2610,25 h50.84
  text ".Layer_Name" at 577,-858.49 h60
Bottom Overlay:
  text ".Layer_Name" at 577,-858.49 h60
Top Paste:
  text ".Layer_Name" at 577,-858.49 h60
Bottom Paste:
  text ".Layer_Name" at 577,-858.49 h60
Top Solder:
  text ".Layer_Name" at 577,-858.49 h60
  text ".Layer_Name" at 577,-858.49 h60
Bottom Solder:
  text ".Layer_Name" at 577,-858.49 h60
Drill Guide:
  text ".Layer_Name" at 577,-858.49 h60
M1 Board Outline:
  lines w5: 0,0 0,2975 3500,2975 3500,0 0,0
  text ".Layer_Name" at 577,-858.49 h60
M2 Board Dimensions:
  rectangle: 0,-275 125,-150
  rectangle: 125,-400 500,-275
  lines w7: 0,-275 1000,-275 ; 125,-400 125,-150 ; 250,-400 250,-150 ; 500,-400 500,-150 ; 750,-400 750,-150 ; 0,-400 1000,-400 1000,-150 0,-150 0,-400
  text ".Layer_Name" at 577,-858.49 h60
M3 3D STEP Top:
  text ".Layer_Name" at 577,-858.49 h60
M4 3D STEP Bottom:
  text ".Layer_Name" at 577,-858.49 h60
M5 Assembly Top:
  lines w10: -292,-930.17 6308,-930.17 ; -292,-726.83 6310,-726.83 ; -292,-523.5 -292,-1133.5 3713,-1133.5 6310,-1133.5 6310,-523.5 -291.5,-523.5 -291.5,-1133.5 1284,-1133.5 ; 2173,-1133.5 2173,-523.5 ; 3440,-726.83 3440,-523.5 ; 4280,-726.83 4280,-523.5 ; 4902,-1140 4902,-937.17
  text "COMPONENTS MARKED 'DNP' SHOULD NOT BE POPULATED." at 1153.5,-318.5 h60
  text "ASSEMBLY VARIANT:" at 1153,-434 h60
  text ".VariantName" at 2189,-434 h60
  text "PCB VIEWED FROM TOP SIDE" at -228.5,-655.67 h60
  text "BOARD #:" at 2248,-655.67 h60
  text ".PRJ_Number" at 2793.5,-655.67 h60
  text "REV:" at 3638,-655.67 h60
  text ".PCB_Rev" at 3929.5,-655.67 h60
  text "SVN REV:" at 4476,-655.67 h60
  text ".VersionControl_RevNumber" at 4982,-655.67 h60
  text "TID #:" at 2248,-859 h60
  text ".TID" at 2793.5,-859 h60
  text "PLOT NAME =" at -228.5,-1064.34 h60
  text ".plot_File_Name" at 577,-1064.34 h60
  text "GENERATED    :" at 2250,-1064.34 h60
  text ".Print_Date" at 3119.5,-1064.34 h60
  text ".Print_Time" at 3848.5,-1064.34 h60
  text "TEXAS INSTRUMENTS" at 5113,-1064.34 h60
M6 Assembly Bottom:
  lines w10: -292.5,-727.33 6309.5,-727.33 ; -290.5,-930.67 6309.5,-930.67 ; 1115.5,-1140.5 1115.5,-937.67 ; 1737.5,-727.33 1737.5,-524 ; 2577.5,-727.33 2577.5,-524 ; 3844.5,-1134 3844.5,-524 ; 4733.5,-1134 6309,-1134 6309,-524 -292.5,-524 -292.5,-1134 2304.5,-1134 6309.5,-1134 6309.5,-524
  text "COMPONENTS MARKED 'DNP' SHOULD NOT BE POPULATED." at 6102,-318 h60
  text ".VariantName" at 5058,-434 h60
  text "ASSEMBLY VARIANT:" at 6097,-434 h60
  text ".VersionControl_RevNumber" at 1035.5,-656.17 h60
  text "SVN REV:" at 1541.5,-656.17 h60
  text ".PCB_Rev" at 2088,-656.17 h60
  text "REV:" at 2379.5,-656.17 h60
  text ".PRJ_Number" at 3224,-656.17 h60
  text "BOARD #:" at 3769.5,-656.17 h60
  text "PCB VIEWED FROM BOTTOM SIDE" at 6246,-656.17 h60
  text ".TID" at 3224,-859.5 h60
  text "TID #:" at 3769.5,-859.5 h60
  text "TEXAS INSTRUMENTS" at 904.5,-1064.84 h60
  text ".Print_Time" at 2169,-1064.84 h60
  text ".Print_Date" at 2898,-1064.84 h60
  text "GENERATED    :" at 3767.5,-1064.84 h60
  text ".plot_File_Name" at 5440.5,-1064.84 h60
  text "PLOT NAME =" at 6246,-1064.84 h60
M9 Title Sheet:
  drawing of 57 lines, arcs and shapes, not listed
  text "1" at 739.84,8036.5 h70
  text "2" at 3235.5,8036.5 h70
  text "3" at 5724.84,8036.5 h70
  text "4" at 8231.51,8036.5 h70
  text "5" at 10730.5,8036.5 h70
  text "6" at 13235.5,8036.5 h70
  text "A" at -416.5,6893.5 h70
  text "A" at 14383.5,6893.5 h70
  text "B" at -416.5,4513.5 h70
  text "B" at 14383.5,4513.5 h70
  text "C" at -416.5,2138.5 h70
  text "C" at 14383.5,2138.5 h70
  text "PROJECT TITLE:" at 11343.5,277.5 h45
  text ".PRJ_Title" at 11393.5,144.17 h70
  text "DESIGNED FOR:" at 11343.5,-23.5 h45
  text ".PRJ_Customer" at 11393.5,-163.5 h70
  text "D" at -416.5,-231.5 h70
  text "D" at 14383.5,-231.5 h70
  text "FILE NAME:" at 11343.5,-323.5 h45
  text ".PCB_File_Name_No_Path" at 11393.5,-443.5 h70
  text "Texas Instruments (TI) and/or its licensors do not warrant the accuracy or completeness of this specification" at 6374,-605.34 h45
  text "ENGINEER:" at 11343.5,-613.5 h45
  text "LAYOUT BY:" at 12848.5,-613.5 h45
  text "or any information contained therein. TI and/or its licensors do not warrant that this design will meet" at 6329.01,-718 h45
  text ".PRJ_Engineer" at 11393.5,-768.49 h70
  text ".PCB_Layout" at 12899,-768.49 h70
  text "the specifications, will be suitable for your application or fit for any particular purpose, or will operate in" at 6329.01,-830.67 h45
  text ".Layer_Name" at 577,-858.49 h60
  text "ALTIUM DESIGNER VERSION:" at 12848.5,-923.5 h45
  text "an implementation. TI and/or its licensors do not warrant that the design is production worthy. You should" at 6329.01,-943.33 h45
  text "completely validate and test your design implementation to confirm the system functionality for your application." at 6374,-1056 h45
  text ".print_Scale" at 11393.5,-1056.83 h70
  text ".Application_BuildNumber" at 12899,-1056.83 h70
  text "1" at 739.84,-1263.5 h70
  text "2" at 3235.5,-1263.5 h70
  text "3" at 5724.84,-1263.5 h70
  text "4" at 8231.51,-1263.5 h70
  text "5" at 10730.5,-1263.5 h70
  text "6" at 13235.5,-1263.5 h70
M10 Fab Notes:
  drawing of 173 lines, arcs and shapes, not listed
  text "DESIGN INFORMATION" at 12378.02,6201 h60
  text "MIN. TRACK WIDTH:" at 11733.46,6021 h60
  text "8" at 12829.7,6021 h60
  text "MIL" at 12984.46,6021 h60
  text "MIN. CLEARANCE:" at 11733.46,5889 h60
  text "0.2" at 12769.7,5889 h60
  text "mm" at 12984.46,5889 h60
  text "MIN. VIA PAD SIZE:" at 11733.46,5757 h60
  text "24" at 12799.71,5757 h60
  text "MIL" at 12984.46,5757 h60
  text "0.05mm (2MIL)" at 12428.46,5615.29 h60
  text "MINIMUM ANNULAR RING" at 11404.23,5611 h60
  text "EXTERNAL" at 13136.46,5611 h60
  text "PER" at 11604.23,5493 h60
  text "IPC-D-275 CLASS 2 LEVEL C" at 11824.23,5493 h60
  text "MIL, HOLES" at 13312.46,5380.71 h60
  text "+/-" at 12920,5380 h60
  text "+/-" at 13774,5380 h60
  text "REGISTRATION TOLERANCES:" at 11404.23,5375 h60
  text "METAL" at 12604,5375 h60
  text "5" at 13180.2,5375 h60
  text "3" at 14013.2,5375 h60
  text "MIL" at 14129.46,5375 h60
  text "+/-" at 13774,5262 h60
  text "HOLE SIZE TOLERANCE (UNLESS OTHERWISE SPECIFIED):" at 11404.23,5257 h60
  text "3" at 14013.2,5257 h60
  text "MIL" at 14129.46,5257 h60
  text "MATERIAL:" at 11329.46,5047.54 h60
  text "FR-4 High Tg" at 12315.9,4907.21 h60
  text "FR-408" at 11750.46,4898.64 h60
  text "OTHER" at 13238.46,4898.64 h60
  text "X" at 12161,4895 h60
  text "62 MIL (1.6mm) +/-10%" at 12070.56,4735.92 h60
  text "THICKNESS:" at 11404.23,4731.64 h60
  text "X" at 11942.4,4731.64 h60
  text "OTHER" at 13355.46,4731.64 h60
  text "TOLERANCE:" at 11404.23,4573.64 h60
  text "X" at 12243.53,4573.64 h60
  text "ANSI IPC-6012 TYPE 3 CLASS 2" at 12430.48,4573.64 h60
  text "OTHER +/-" at 12430.46,4417.64 h60
  text "BOW & TWIST:" at 11404.23,4260.64 h60
  text "X" at 12243.53,4260.64 h60
  text "ANSI IPC-6012 TYPE 3 CLASS 2" at 12430.48,4260.64 h60
  text "OTHER +/-" at 12430.46,4102.13 h60
  text "DRILLING:" at 11329.46,3963.64 h60
  text "REFERENCE:" at 11404.23,3846.64 h60
  text "X" at 12052.46,3846.64 h60
  text "AS SHOWN" at 12239.46,3846.64 h60
  text "X" at 12953.46,3846.64 h60
  text "NC_DRILL FILES" at 13090.46,3846.64 h60
  text "PTH COPPER THICKNESS:" at 11404.23,3688.64 h60
  text "X" at 12534.46,3688.64 h60
  text "20-30 um" at 12671.46,3688.64 h60
  text "OTHER" at 13388.46,3688.64 h60
  text "BOARD FINISH:" at 11329.46,3529.64 h60
  text "SILKSCREEN:" at 11484.68,3411.64 h60
  text "X" at 12433.46,3411.64 h60
  text "TOP" at 12559.46,3411.64 h60
  text "X" at 12943.46,3411.64 h60
  text "BOTTOM" at 13070.46,3411.64 h60
  text "SILKSCREEN COLOR:" at 11484.68,3244.64 h60
  text "X" at 12432.42,3244.64 h60
  text "WHITE" at 12559.46,3244.64 h60
  text "OTHER" at 13070.46,3244.64 h60
  text "X" at 12563.42,3085.44 h60
  text "GREEN" at 12690.46,3085.44 h60
  text "OTHER" at 13308.46,3085.44 h60
  text "SOLDER RESIST COLOR:" at 11484.68,3074.64 h60
  text "X" at 12563.42,2915.44 h60
  text "MATTE" at 12690.46,2915.44 h60
  text "SEMI-GLOSS" at 13308,2914.8 h60
  text "IMMERSION GOLD (ENIG)" at 12390.46,2726.92 h60
  text "ENEPIG" at 13728,2723.64 h60
  text "SURFACE FINISH:" at 11329.46,2722.64 h60
  text "X" at 12203.51,2722.64 h60
  text "IMM. TIN/SILVER OR EQUIV" at 11659,2565.64 h60
  text "OTHER" at 13090.46,2565.64 h60
  text "ARRAY/PANEL:" at 11329.46,2386.64 h60
  text "CUT AND TRIM PER M1 BOARD OUTLINE" at 12390.46,2382.35 h60
  text "N.C. ROUTE" at 12390.46,2230.64 h60
  text "X" at 13069.46,2230.64 h60
  text "V. SCORE" at 13256.46,2230.64 h60
  text "CERTIFICATION:" at 11329.46,2093.64 h60
  text "MATERIALS AND WORKMANSHIP FOR ALL PCBS" at 12054.46,2093.64 h60
  text "TO MEET OR EXCEED THE REQUIREMENTS OF:" at 12054.46,1995.64 h60
  text "X" at 11680.96,1859.13 h60
  text "ANSI IPC-A-600F CLASS ->" at 11819.96,1859.13 h60
  text "X" at 13459.02,1859.13 h60
  text "2" at 13577.96,1859.14 h60
  text "1" at 13262.96,1857.64 h60
  text "3" at 13931.96,1857.64 h60
  text "X" at 12495.02,1699.64 h60
  text "RoHS" at 12631.96,1699.64 h60
  text "OTHER" at 13276.36,1699.64 h60
  text "PER ORDER" at 13673.42,1699.64 h60
  text "ALL BOARDS MUST MEET OR EXCEED UL94-V0 REQUIREMENTS." at 11357,1534 h60
  text "PCB MUST BEAR THE UL94V-0 UL REGISTERED MATERIAL ID NUMBER" at 11357,1414 h60
  text "ADDITIONAL REQUIREMENTS:" at 11329.46,1240.64 h60
  text "MICROSECTION:" at 11404.23,1125.64 h60
  text "YES" at 12309.96,1125.64 h60
  text "REQUIRED" at 13171.46,969.49 h60
  text "BARE BOARD ELEC. TEST:" at 11404.23,966.64 h60
  text "NONE" at 12709.96,966.64 h60
  text "X" at 13044.46,966.64 h60
  text "PER ORDER" at 13763.46,966.64 h60
  text ".Layer_Name" at 577,-858.49 h60
M11 Gerber Information:
  lines w10: -292,-930.17 6308,-930.17 ; -292,-726.83 6310,-726.83 ; -292,-523.5 -292,-1133.5 3713,-1133.5 6310,-1133.5 6310,-523.5 -291.5,-523.5 -291.5,-1133.5 1284,-1133.5 ; 2173,-1133.5 2173,-523.5 ; 3440,-726.83 3440,-523.5 ; 4280,-726.83 4280,-523.5 ; 4902,-1140 4902,-937.17
  text "ALL ARTWORK VIEWED FROM TOP SIDE" at -228.5,-655.67 h60
  text "BOARD #:" at 2248,-655.67 h60
  text ".PRJ_Number" at 2793.5,-655.67 h60
  text "REV:" at 3638,-655.67 h60
  text ".PCB_Rev" at 3929.5,-655.67 h60
  text "SVN REV:" at 4476,-655.67 h60
  text ".VersionControl_RevNumber" at 4982,-655.67 h60
  text "LAYER NAME =" at -228.5,-858.49 h60
  text "TID #:" at 2248,-859 h60
  text ".TID" at 2793.5,-859 h60
  text "PLOT NAME =" at -228.5,-1064.34 h60
  text ".plot_File_Name" at 577,-1064.34 h60
  text "GENERATED    :" at 2250,-1064.34 h60
  text ".Print_Date" at 3119.5,-1064.34 h60
  text ".Print_Time" at 3848.5,-1064.34 h60
  text "TEXAS INSTRUMENTS" at 5113,-1064.34 h60
M12 Stackup:
  drawing of 191 lines, arcs and shapes, not listed
  text "Layer" at 9790.34,7830 h60
  text "Name" at 10200.26,7830 h60
  text "Material" at 11130,7830 h60
  text "Thickness" at 11989.77,7830 h60
  text "Constant" at 12639.6,7830 h60
  text "Board Layer Stack" at 13209.46,7830 h60
  text "1" at 9790.34,7710 h60
  text "Top Overlay" at 10200.26,7710 h60
  text "2" at 9790.34,7590 h60
  text "Top Solder" at 10200.26,7590 h60
  text "Solder Resist" at 11130,7590 h60
  text "0.40mil" at 11989.77,7590 h60
  text "3.5" at 12639.6,7590 h60
  text "3" at 9790.34,7470 h60
  text "Top Layer" at 10200.26,7470 h60
  text "Copper" at 11130,7470 h60
  text "1.40mil" at 11989.77,7470 h60
  text "4" at 9790.34,7350 h60
  text "Dielectric1" at 10200.26,7350 h60
  text "FR-4" at 11130,7350 h60
  text "59.20mil" at 11989.77,7350 h60
  text "4.8" at 12639.6,7350 h60
  text "5" at 9790.34,7230 h60
  text "Bottom Layer" at 10200.26,7230 h60
  text "Copper" at 11130,7230 h60
  text "1.40mil" at 11989.77,7230 h60
  text "6" at 9790.34,7110 h60
  text "Bottom Solder" at 10200.26,7110 h60
  text "Solder Resist" at 11130,7110 h60
  text "0.40mil" at 11989.77,7110 h60
  text "3.5" at 12639.6,7110 h60
  text "7" at 9790.34,6990 h60
  text "Bottom Overlay" at 10200.26,6990 h60
  text ".Layer_Name" at 577,-858.49 h60
M13 Component Bodies Top:
  text ".Layer_Name" at 577,-858.49 h60
M14 Component Bodies Bottom:
  text ".Layer_Name" at 577,-858.49 h60
M15 Courtyards Top:
  text ".Layer_Name" at 577,-858.49 h60
M16 Courtyards Bottom:
  text ".Layer_Name" at 577,-858.49 h60
Drill Drawing:
  text ".Layer_Name" at 577,-858.49 h60
M17 Embedded Cavity:
  text ".Layer_Name" at 577,-858.49 h60
M18 Embedded Assembly:
  text ".Layer_Name" at 577,-858.49 h60
M19 Embedded Keepout:
  text ".Layer_Name" at 577,-858.49 h60

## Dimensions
0,2975 to 0,0 on M2 Board Dimensions
0,-400 to 1000,-400 on M2 Board Dimensions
